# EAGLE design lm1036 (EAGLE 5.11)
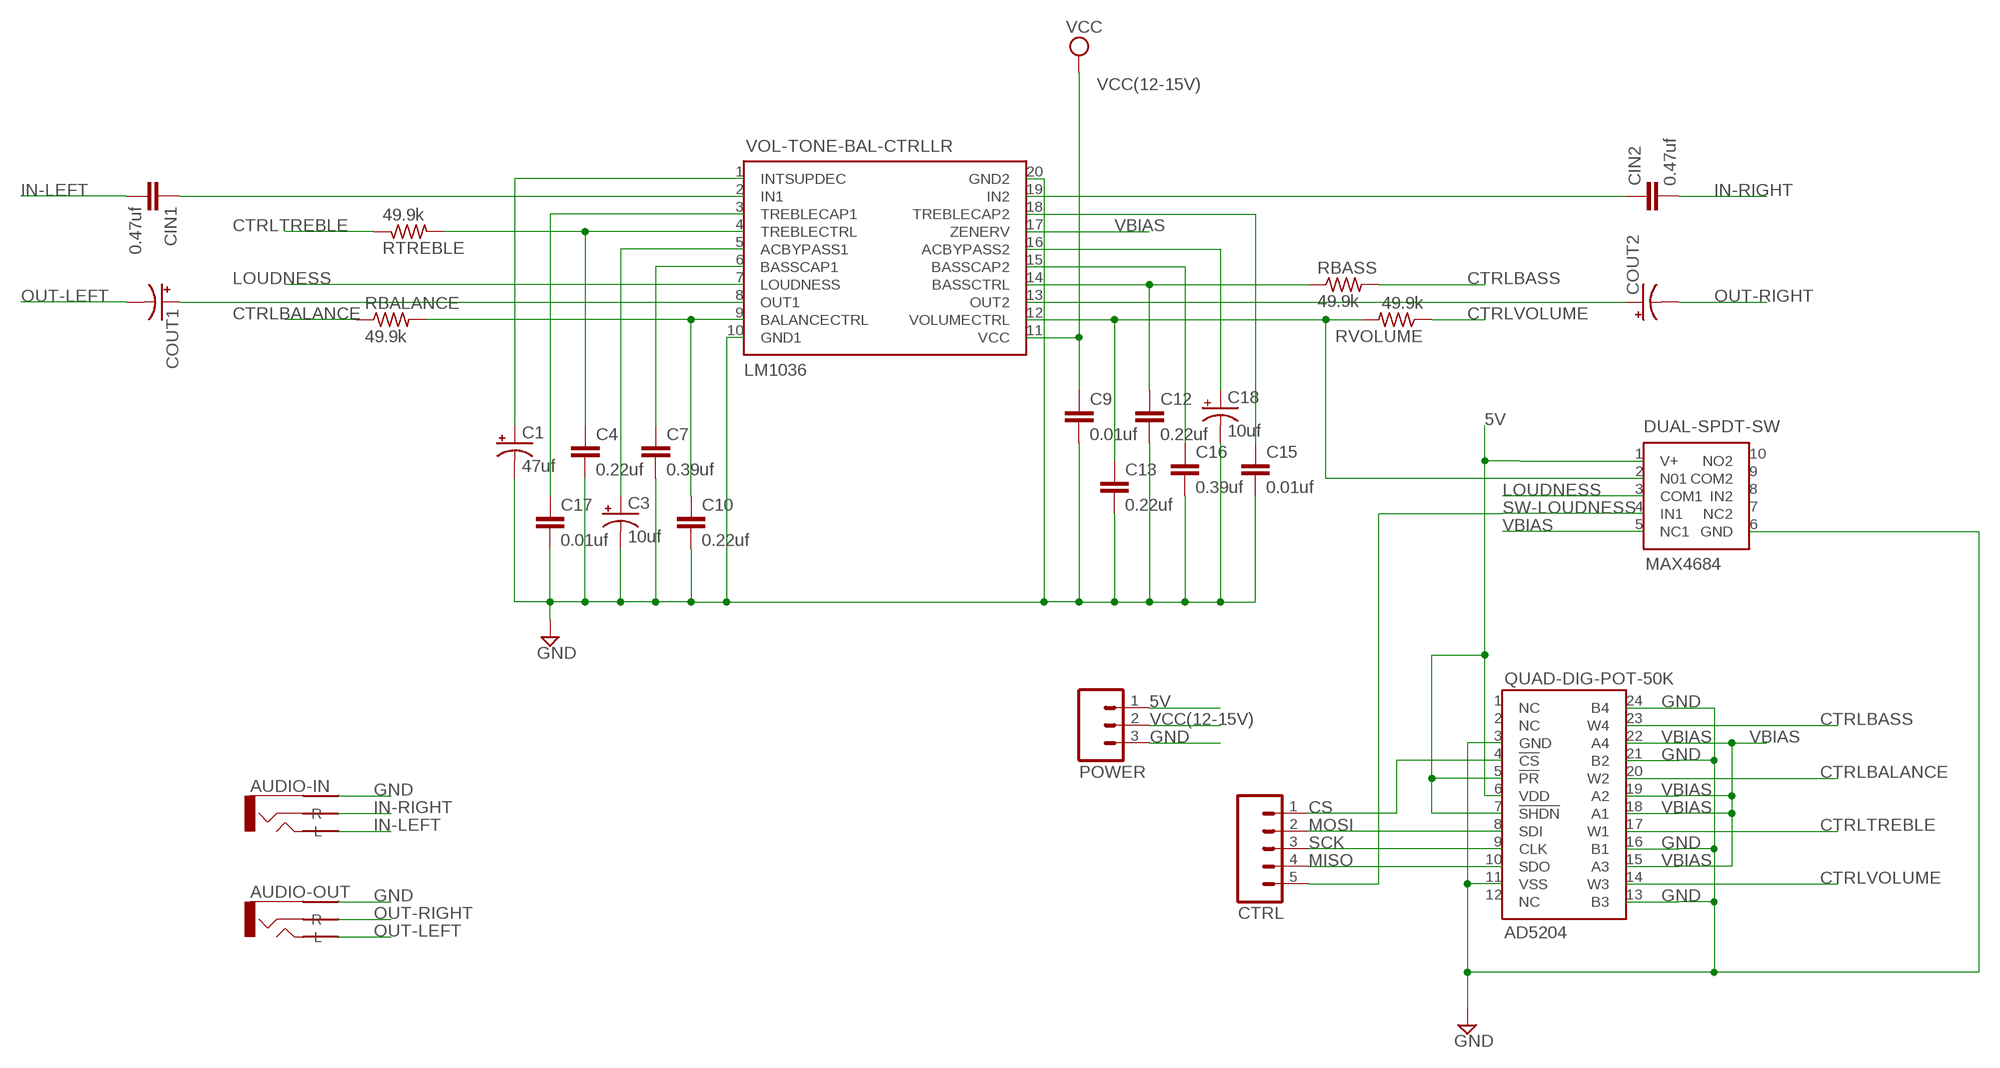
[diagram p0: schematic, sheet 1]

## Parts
AUDIO-IN  AUDIO-JACK-STEREO-3PIN948  [AUDIO-JACK-STEREO-3PIN-948]
AUDIO-OUT  AUDIO-JACK-STEREO-3PIN948  [AUDIO-JACK-STEREO-3PIN-948]
C1  47uf  CPOL-USE3.5-8  [E3,5-8]
C3  10uf  CPOL-USE3.5-8  [E3,5-8]
C4  0.22uf  C-EUC0805  [C0805]
C7  0.39uf  C-EUC1206  [C1206]
C9  0.01uf  C-EUC1206  [C1206]
C10  0.22uf  C-EUC0805  [C0805]
C12  0.22uf  C-EUC0805  [C0805]
C13  0.22uf  C-EUC0805  [C0805]
C15  0.01uf  C-EUC1206  [C1206]
C16  0.39uf  C-EUC1206  [C1206]
C17  0.01uf  C-EUC1206  [C1206]
C18  10uf  CPOL-USE3.5-8  [E3,5-8]
CIN1  0.47uf  C-EUC1206  [C1206]
CIN2  0.47uf  C-EUC1206  [C1206]
COUT1  CPOL-USE3.5-8  [E3,5-8]
COUT2  CPOL-USE3.5-8  [E3,5-8]
CTRL  M05PTH  [1X05]
DUAL-SPDT-SW  MAX4684  [UMAX10]
POWER  M03PTH  [1X03]
QUAD-DIG-POT-50K  AD5204  [DIL24-3]
RBALANCE  49.9k  R-US_R0805  [R0805]
RBASS  49.9k  R-US_R0805  [R0805]
RTREBLE  49.9k  R-US_R0805  [R0805]
RVOLUME  49.9k  R-US_R0805  [R0805]
VOL-TONE-BAL-CTRLLR  LM1036  [DIL20]

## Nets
5V: DUAL-SPDT-SW.1(V+) POWER.1 QUAD-DIG-POT-50K.5(!PR) QUAD-DIG-POT-50K.6(VDD) QUAD-DIG-POT-50K.7(!SHDN)
CS: CTRL.1 QUAD-DIG-POT-50K.4(!CS)
CTRLBALANCE: QUAD-DIG-POT-50K.20(W2) RBALANCE.1
CTRLBASS: QUAD-DIG-POT-50K.23(W4) RBASS.2
CTRLTREBLE: QUAD-DIG-POT-50K.17(W1) RTREBLE.1
CTRLVOLUME: QUAD-DIG-POT-50K.14(W3) RVOLUME.1
GND: AUDIO-IN.1(COM) AUDIO-OUT.1(COM) C1.- C3.- C4.2 C7.2 C9.2 C10.2 C12.2 C13.2 C15.2 C16.2 C17.2 C18.- DUAL-SPDT-SW.6(GND) POWER.3 QUAD-DIG-POT-50K.3(GND) QUAD-DIG-POT-50K.11(VSS) QUAD-DIG-POT-50K.13(B3) QUAD-DIG-POT-50K.16(B1) QUAD-DIG-POT-50K.21(B2) QUAD-DIG-POT-50K.24(B4) VOL-TONE-BAL-CTRLLR.10(GND1) VOL-TONE-BAL-CTRLLR.20(GND2)
IN-LEFT: AUDIO-IN.2(L) CIN1.2
IN-RIGHT: AUDIO-IN.3(R) CIN2.2
LOUDNESS: DUAL-SPDT-SW.3(COM1) VOL-TONE-BAL-CTRLLR.7(LOUDNESS)
MISO: CTRL.4 QUAD-DIG-POT-50K.10(SDO)
MOSI: CTRL.2 QUAD-DIG-POT-50K.8(SDI)
N$1: C1.+ VOL-TONE-BAL-CTRLLR.1(INTSUPDEC)
N$2: CIN1.1 VOL-TONE-BAL-CTRLLR.2(IN1)
N$3: C17.1 VOL-TONE-BAL-CTRLLR.3(TREBLECAP1)
N$4: C7.1 VOL-TONE-BAL-CTRLLR.6(BASSCAP1)
N$5: COUT2.+ VOL-TONE-BAL-CTRLLR.13(OUT2)
N$6: C4.1 RTREBLE.2 VOL-TONE-BAL-CTRLLR.4(TREBLECTRL)
N$7: COUT1.+ VOL-TONE-BAL-CTRLLR.8(OUT1)
N$8: CIN2.1 VOL-TONE-BAL-CTRLLR.19(IN2)
N$9: C12.1 RBASS.1 VOL-TONE-BAL-CTRLLR.14(BASSCTRL)
N$10: C10.1 RBALANCE.2 VOL-TONE-BAL-CTRLLR.9(BALANCECTRL)
N$12: C3.+ VOL-TONE-BAL-CTRLLR.5(ACBYPASS1)
N$13: C16.1 VOL-TONE-BAL-CTRLLR.15(BASSCAP2)
N$14: C18.+ VOL-TONE-BAL-CTRLLR.16(ACBYPASS2)
N$16: C15.1 VOL-TONE-BAL-CTRLLR.18(TREBLECAP2)
N$18: C13.1 DUAL-SPDT-SW.2(N01) RVOLUME.2 VOL-TONE-BAL-CTRLLR.12(VOLUMECTRL)
OUT-LEFT: AUDIO-OUT.2(L) COUT1.-
OUT-RIGHT: AUDIO-OUT.3(R) COUT2.-
SCK: CTRL.3 QUAD-DIG-POT-50K.9(CLK)
SW-LOUDNESS: CTRL.5 DUAL-SPDT-SW.4(IN1)
VBIAS: DUAL-SPDT-SW.5(NC1) QUAD-DIG-POT-50K.15(A3) QUAD-DIG-POT-50K.18(A1) QUAD-DIG-POT-50K.19(A2) QUAD-DIG-POT-50K.22(A4) VOL-TONE-BAL-CTRLLR.17(ZENERV)
VCC(12-15V): C9.1 POWER.2 VOL-TONE-BAL-CTRLLR.11(VCC) ; supply symbol labelled VCC
Unconnected: DUAL-SPDT-SW.7(NC2) DUAL-SPDT-SW.8(IN2) DUAL-SPDT-SW.9(COM2) DUAL-SPDT-SW.10(NO2) QUAD-DIG-POT-50K.1(NC) QUAD-DIG-POT-50K.2(NC) QUAD-DIG-POT-50K.12(NC)

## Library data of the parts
AUDIO-IN AUDIO-OUT = trl:AUDIO-JACK-STEREO-3PIN
C1 C3 C18 COUT1 COUT2 = rcl:CPOL-US: POLARIZED CAPACITOR, American symbol
C4 C7 C9 C10 C12 C13 C15-C17 CIN1 CIN2 = rcl:C-EU: CAPACITOR, European symbol
CTRL = SparkFun:M05: Header 5 Standard 5-pin 0.1" header. Use with straight break away headers (SKU : PRT-00116), right angle break away headers (PRT-00553), swiss pins (PRT-00743), machine pins (PRT-00117), and female headers (PRT-00115). Molex polarized connector foot print use with SKU : PRT-08230 with associated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
DUAL-SPDT-SW = trl:MAX4684
POWER = SparkFun:M03: Header 3 Standard 3-pin 0.1" header. Use with straight break away headers (SKU : PRT-00116), right angle break away headers (PRT-00553), swiss pins (PRT-00743), machine pins (PRT-00117), and female headers (PRT-00115). Molex polarized connector foot print use with SKU : PRT-08232 with associated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
QUAD-DIG-POT-50K = trl:AD5204
RBALANCE RBASS RTREBLE RVOLUME = rcl:R-US_: RESISTOR, American symbol
VOL-TONE-BAL-CTRLLR = trl:LM1036

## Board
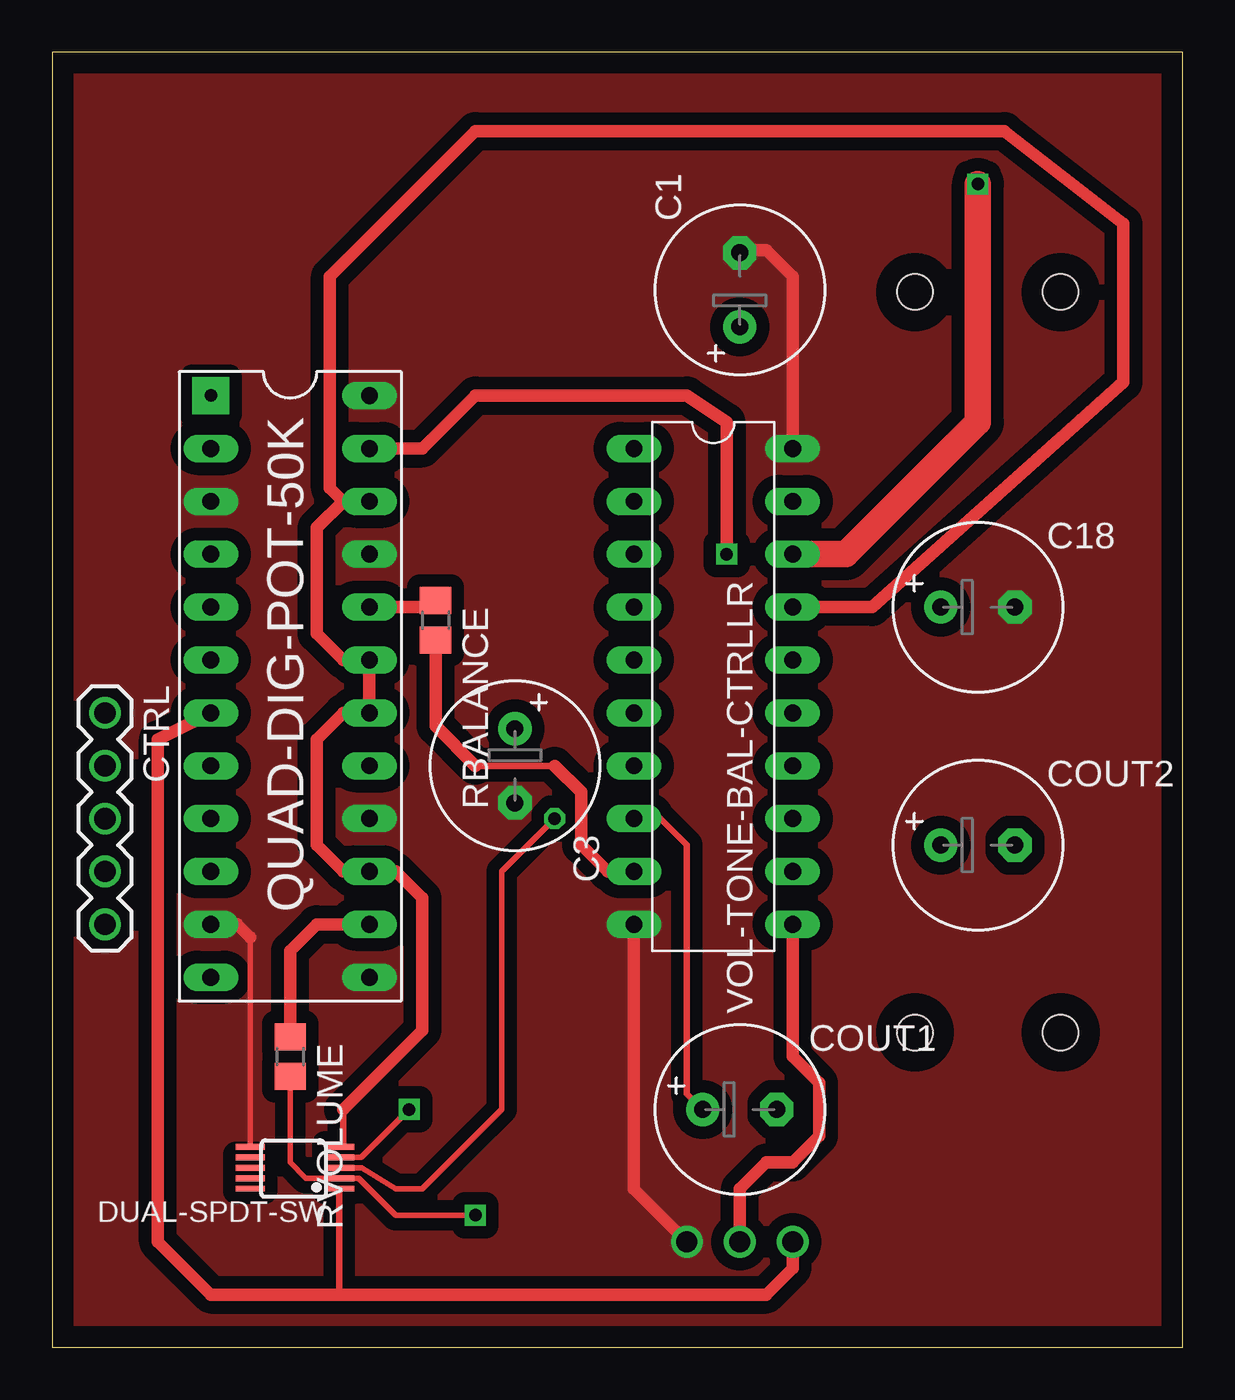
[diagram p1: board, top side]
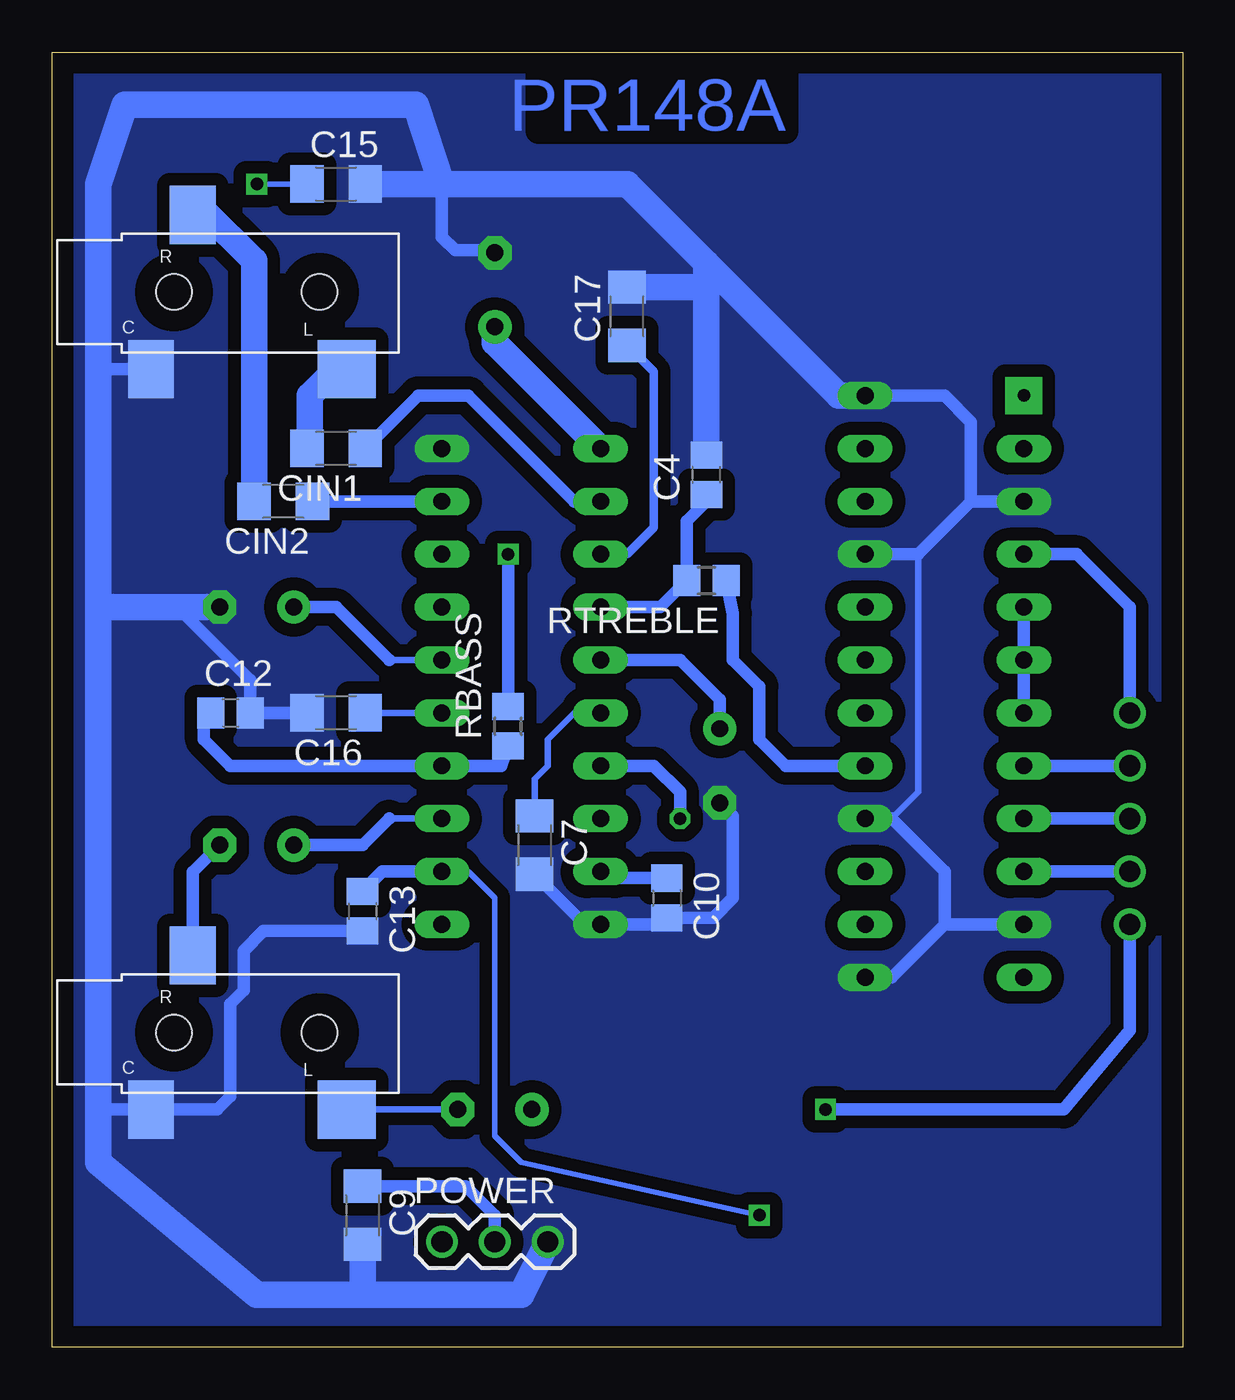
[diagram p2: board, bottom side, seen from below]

Size 54.28 x 62.22 mm. Coordinates in mm from the lower left corner, seen from the top.
Outline: 0,0 54.28,0 54.28,62.22 0,62.22 0,0
Copper layers (1*16): Top 0.035mm / dielectric 1.5mm / Bottom 0.035mm
Design rules "default": minimum track width 10mil, minimum drill 24mil, track to track 8mil, track to pad 8mil, pad to pad 8mil, via to via 8mil, smd to smd 8mil, copper to edge 40mil, drill to drill 8mil, minimum pad ring 10mil, minimum via ring 8mil, stop-mask expansion 4mil, vias tented up to drill 0mil, thermal gap 10mil

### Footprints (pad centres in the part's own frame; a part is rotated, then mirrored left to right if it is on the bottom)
AUDIO-JACK-STEREO-3PIN-948 = smd 2.2 x 2.8: 1 -3.81,-3.81; 3 -1.81,3.59 | smd 2.8 x 2.8: 2 5.59,-3.81 | hole 1.7: -2.71,-0.11; 4.29,-0.11
E3,5-8 = drill 0.813 pad 1.6 round: + -1.778,0 | drill 0.813 pad 1.6 octagon: - 1.778,0
C0805 = smd 1.3 x 1.5: 1 -0.95,0; 2 0.95,0
C1206 = smd 1.6 x 1.8: 1 -1.4,0; 2 1.4,0
1X05 = drill 1.016 round: 1 0,0; 2 2.54,0; 3 5.08,0; 4 7.62,0; 5 10.16,0
UMAX10 = smd 1.4 x 0.28: 1 -2.37,1.26; 2 -2.37,0.76; 3 -2.37,0.26; 4 -2.37,-0.24; 5 -2.37,-0.74; 6 1.91,-0.74; 7 1.91,-0.24; 8 1.91,0.26; 9 1.91,0.76; 10 1.91,1.26
1X03 = drill 1.016 round: 1 0,0; 2 2.54,0; 3 5.08,0
DIL24-3 = drill 0.6 pad 1.778 square: 1 -12.7,-7.62 | drill 0.813 long: 2 -10.16,-7.62; 3 -7.62,-7.62; 4 -5.08,-7.62; 5 -2.54,-7.62; 6 0,-7.62; 7 2.54,-7.62; 8 5.08,-7.62; 9 7.62,-7.62; 10 10.16,-7.62; 11 12.7,-7.62; 12 15.24,-7.62; 13 15.24,0; 14 12.7,0; 15 10.16,0; 16 7.62,0; 17 5.08,0; 18 2.54,0; 19 0,0; 20 -2.54,0; 21 -5.08,0; 22 -7.62,0; 23 -10.16,0; 24 -12.7,0
R0805 = smd 1.3 x 1.5: 1 -0.95,0; 2 0.95,0
DIL20 = drill 0.813 long: 1 -11.43,-3.81; 2 -8.89,-3.81; 3 -6.35,-3.81; 4 -3.81,-3.81; 5 -1.27,-3.81; 6 1.27,-3.81; 7 3.81,-3.81; 8 6.35,-3.81; 9 8.89,-3.81; 10 11.43,-3.81; 11 11.43,3.81; 12 8.89,3.81; 13 6.35,3.81; 14 3.81,3.81; 15 1.27,3.81; 16 -1.27,3.81; 17 -3.81,3.81; 18 -6.35,3.81; 19 -8.89,3.81; 20 -11.43,3.81

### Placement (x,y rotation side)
AUDIO-IN  45.72,50.8 0 bottom
AUDIO-OUT  45.72,15.24 0 bottom
C1  33.02,50.8 90 top
C3  22.23,27.94 270 top
C4  22.86,41.91 90 bottom
C7  31.11,24.13 270 bottom
C9  39.37,6.35 270 bottom
C10  24.77,21.59 270 bottom
C12  45.72,30.48 0 bottom
C13  39.37,20.95 270 bottom
C15  40.64,55.88 0 bottom
C16  40.64,30.48 180 bottom
C17  26.67,49.53 90 bottom
C18  44.45,35.56 0 top
CIN1  40.64,43.18 180 bottom
CIN2  43.18,40.64 180 bottom
COUT1  33.02,11.43 0 top
COUT2  44.45,24.13 0 top
CTRL  2.54,30.48 270 top
DUAL-SPDT-SW  11.43,8.89 180 top
POWER  35.56,5.08 0 bottom
QUAD-DIG-POT-50K  15.24,33.02 270 top
RBALANCE  18.41,34.92 270 top
RBASS  32.38,29.84 90 bottom
RTREBLE  22.86,36.83 180 bottom
RVOLUME  11.43,13.97 270 top
VOL-TONE-BAL-CTRLLR  31.75,31.75 270 top

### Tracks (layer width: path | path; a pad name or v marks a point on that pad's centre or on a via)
5V
  Top 0.254: 13.97,2.54 13.8,2.71
  Top 0.305: 13.8,2.71 DUAL-SPDT-SW.1
  Top 0.61: QUAD-DIG-POT-50K.7 5.08,29.21 5.08,5.08 7.62,2.54 13.97,2.54 34.29,2.54 35.56,3.81 POWER.1
  Bottom 0.61: QUAD-DIG-POT-50K.5 QUAD-DIG-POT-50K.6 QUAD-DIG-POT-50K.7
CS
  Bottom 0.61: CTRL.1 2.54,35.56 5.08,38.1 QUAD-DIG-POT-50K.4
CTRLBALANCE
  Top 0.61: QUAD-DIG-POT-50K.20 18.1,35.56 RBALANCE.1
CTRLBASS  (via drill 0.6)
  Top 0.61: v32.38,38.1 32.38,44.45 30.48,45.72 20.32,45.72 17.78,43.18 QUAD-DIG-POT-50K.23
  Bottom 0.61: v32.38,38.1 RBASS.2
CTRLTREBLE
  Bottom 0.61: RTREBLE.1 21.59,35.24 21.59,33.02 20.32,31.75 20.32,29.21 19.05,27.94 QUAD-DIG-POT-50K.17
CTRLVOLUME
  Top 0.61: RVOLUME.1 11.43,19.05 12.7,20.32 QUAD-DIG-POT-50K.14
GND
  Top 0.254: DUAL-SPDT-SW.6 9.52,19.69
  Top 0.61: 9.52,19.69 8.89,20.32 QUAD-DIG-POT-50K.11 | VOL-TONE-BAL-CTRLLR.20 35.56,51.44 34.29,52.7 33.15,52.7 C1.- | VOL-TONE-BAL-CTRLLR.10 27.94,7.62 POWER.3
  Bottom 0.305: 13.97,25.4 12.7,26.67 12.7,38.1 | 25.09,20.32 C10.2
  Bottom 0.61: 52.07,11.43 AUDIO-OUT.1 46.35,11.43 45.72,12.06 45.72,16.51 45.09,17.14 45.09,19.05 44.13,20 C13.2 | 46.99,35.56 46.67,35.24 | 52.07,46.99 AUDIO-IN.1 | 10.16,40.64 QUAD-DIG-POT-50K.3 | 10.16,40.64 12.7,38.1 QUAD-DIG-POT-50K.21 | QUAD-DIG-POT-50K.24 11.43,45.72 10.16,44.45 10.16,40.64 | QUAD-DIG-POT-50K.11 11.43,20.32 | 11.43,20.32 13.97,17.78 QUAD-DIG-POT-50K.13 | QUAD-DIG-POT-50K.16 13.97,25.4 11.43,22.86 11.43,20.32 | C16.2 C12.2 44.77,32.07 48.26,35.56 | 35.56,55.88 35.56,53.34 34.92,52.7 33.15,52.7 C1.- | 25.09,20.32 VOL-TONE-BAL-CTRLLR.10 28.7,20.32 C7.2 | C10.2 22.54,20.64 21.59,21.59 21.59,25.53 C3.-
  Bottom 1.27: 52.07,35.56 48.26,35.56 46.99,35.56 C18.- | 52.07,35.56 52.07,46.99 52.07,55.88 50.8,59.69 36.83,59.69 35.56,55.88 | 52.07,35.56 52.07,11.43 52.07,8.89 44.45,2.54 39.37,2.54 | POWER.3 31.75,2.54 39.37,2.54 | 39.37,2.54 C9.2 | 35.56,55.88 C15.2 | QUAD-DIG-POT-50K.24 16.51,45.72 22.86,52.07 | 22.86,52.07 26.67,55.88 35.56,55.88 | 22.86,52.07 22.86,50.8 | 22.86,50.8 C4.2 | C17.2 22.99,50.93 22.86,50.8
  pour Top (isolate 0.61, no thermals): 0,62.23 54.61,62.23 54.61,0 0,0
  pour Bottom (isolate 0.61, no thermals): 0,62.23 54.61,62.23 54.61,0 0,0
IN-LEFT
  Bottom 1.27: AUDIO-IN.2 40.64,46.99 41.91,45.72 41.91,43.31 CIN1.2
IN-RIGHT
  Bottom 1.27: CIN2.2 44.58,52.2 46.99,54.61 47.31,54.61 AUDIO-IN.3
LOUDNESS  (via drill 0.6)
  Top 0.254: DUAL-SPDT-SW.3 14.87,8.63 16.51,7.62 17.78,7.62 21.59,11.43 21.59,22.86 v24.13,25.4
  Bottom 0.61: v24.13,25.4 24.13,26.67 25.4,27.94 VOL-TONE-BAL-CTRLLR.7
MISO
  Bottom 0.61: CTRL.4 QUAD-DIG-POT-50K.10
MOSI
  Bottom 0.61: CTRL.2 QUAD-DIG-POT-50K.8
N$1
  Bottom 1.27: VOL-TONE-BAL-CTRLLR.1 33.02,48.26 C1.+
N$2
  Bottom 0.61: VOL-TONE-BAL-CTRLLR.2 29.21,40.64 34.29,45.72 36.7,45.72 CIN1.1
N$3
  Bottom 0.406: VOL-TONE-BAL-CTRLLR.3 26.67,38.1 25.4,39.37 25.4,46.86 C17.1
N$4
  Bottom 0.305: C7.1 31.11,27.3 30.48,27.94 30.48,29.21 29.21,30.48 VOL-TONE-BAL-CTRLLR.6
N$5
  Bottom 0.305: VOL-TONE-BAL-CTRLLR.13 38.1,25.4
  Bottom 0.61: COUT2.+ 39.37,24.13 38.1,25.4
N$6
  Bottom 0.305: 22.86,40.64 C4.1
  Bottom 0.61: VOL-TONE-BAL-CTRLLR.4 25.08,35.56 RTREBLE.2 23.81,39.69 22.86,40.64
N$7
  Top 0.305: VOL-TONE-BAL-CTRLLR.8 29.21,25.4 30.48,24.13 30.48,12.19 COUT1.+
N$8
  Bottom 0.61: VOL-TONE-BAL-CTRLLR.19 CIN2.1
N$9
  Bottom 0.61: RBASS.1 32.7,27.94 VOL-TONE-BAL-CTRLLR.14 45.72,27.94 46.99,29.21 46.99,30.16 C12.1
N$10
  Top 0.305: 24.13,27.94 20.32,27.94
  Top 0.61: RBALANCE.2 18.41,29.84 20.32,27.94 | 24.13,27.94 25.4,26.67 25.4,24.13 26.67,22.86 VOL-TONE-BAL-CTRLLR.9
  Bottom 0.61: C10.1 27.62,22.54 VOL-TONE-BAL-CTRLLR.9
N$12
  Bottom 0.61: C3.+ 22.23,31.11 24.13,33.02 VOL-TONE-BAL-CTRLLR.5
N$13
  Bottom 0.305: VOL-TONE-BAL-CTRLLR.15 C16.1
N$14
  Bottom 0.305: VOL-TONE-BAL-CTRLLR.16 38.1,33.02
  Bottom 0.61: 38.1,33.02 40.64,35.56 C18.+
N$16  (via drill 0.6)
  Top 1.27: VOL-TONE-BAL-CTRLLR.18 38.1,38.1 44.45,44.45 v44.45,55.88
  Bottom 0.254: v44.45,55.88 C15.1
N$18  (via drill 0.6)
  Top 0.254: RVOLUME.2 11.43,8.89 12.19,8.13 DUAL-SPDT-SW.2 14.73,8.13 16.51,6.35 v20.32,6.35
  Bottom 0.254: VOL-TONE-BAL-CTRLLR.12 34.29,22.86 33.02,21.59 33.02,10.16 31.75,8.89 v20.32,6.35
  Bottom 0.61: VOL-TONE-BAL-CTRLLR.12 38.41,22.86 C13.1
OUT-LEFT
  Bottom 0.305: COUT1.- AUDIO-OUT.2
OUT-RIGHT
  Bottom 0.61: AUDIO-OUT.3 47.53,22.83 COUT2.-
SCK
  Bottom 0.61: CTRL.3 QUAD-DIG-POT-50K.9
SW-LOUDNESS  (via drill 0.6)
  Top 0.254: DUAL-SPDT-SW.4 14.85,9.13 v17.14,11.43
  Bottom 0.61: v17.14,11.43 5.71,11.43 2.54,15.24 CTRL.5
VBIAS
  Top 0.305: 13.97,40.64 QUAD-DIG-POT-50K.22 | 13.97,11.43 13.97,9.8 DUAL-SPDT-SW.5
  Top 0.61: VOL-TONE-BAL-CTRLLR.17 39.37,35.56 51.44,46.35 51.44,53.98 45.72,58.42 20.32,58.42 13.34,51.44 13.34,41.27 13.97,40.64 12.7,39.37 12.7,34.29 13.97,33.02 QUAD-DIG-POT-50K.19 QUAD-DIG-POT-50K.18 13.97,30.48 12.7,29.21 12.7,24.13 13.97,22.86 QUAD-DIG-POT-50K.15 16.51,22.86 17.78,21.59 17.78,15.24 13.97,11.43
VCC(12-15V)
  Top 0.61: VOL-TONE-BAL-CTRLLR.11 35.56,13.97 36.83,12.7 36.83,10.16 35.56,8.89 34.29,8.89 33.02,7.62 POWER.2
  Bottom 0.305: C9.1 39.5,7.62
  Bottom 0.61: C9.1 34.42,7.75 33.02,6.35 POWER.2

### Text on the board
Bottom: PR148A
